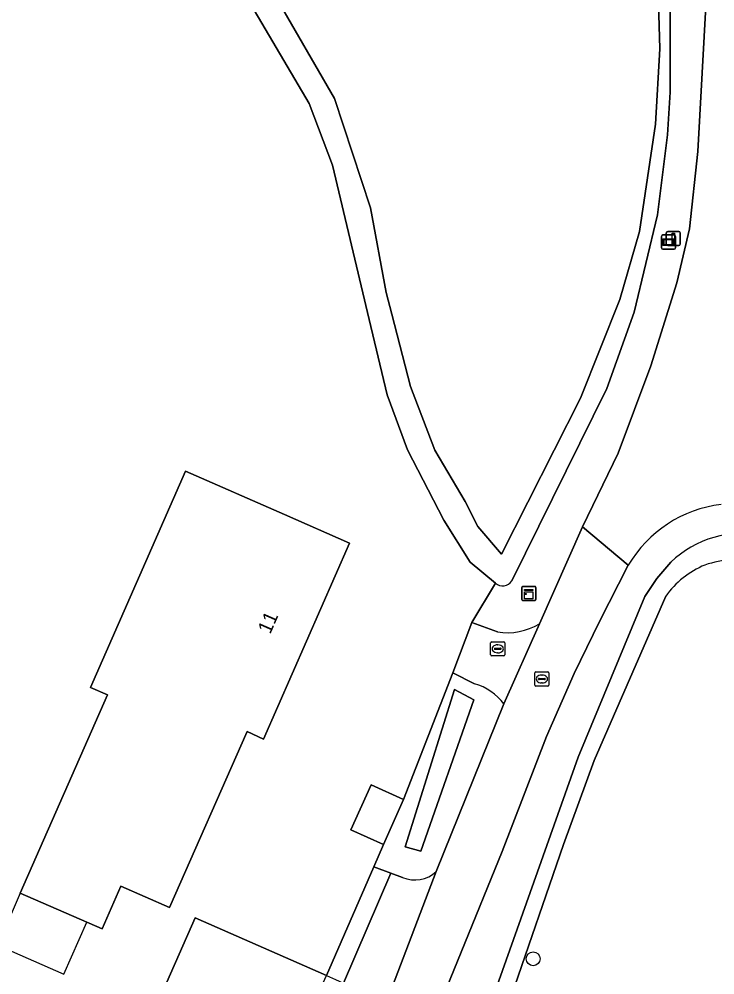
# Model space of a CAD drawing. Extents: x 163859 to 164644, y 379566 to 382155.
# Drawn here: x 164389 to 164438.1, y 381270.8 to 381338.2 of the extents above; entities that cross this region are included whole.
import ezdxf

# ---------------------------------------------------------------- set-up
doc = ezdxf.new("R2010")
doc.units = 0
for name, color, linetype in [('IMGEO_Boom', 7, 'Continuous'), ('IMGEO_Erf', 7, 'Continuous'), ('IMGEO_Groenvoorziening', 7, 'Continuous'), ('IMGEO_Kast', 7, 'Continuous'), ('IMGEO_Pand', 7, 'Continuous'), ('IMGEO_Pand_nummerreeks', 7, 'Continuous'), ('IMGEO_Pand_overbouw', 7, 'Continuous'), ('IMGEO_Rijbaan_lokaal_gesloten', 7, 'Continuous'), ('IMGEO_Rioolput', 7, 'Continuous'), ('IMGEO_Verkeersbordpaal', 7, 'Continuous'), ('IMGEO_Verklikker', 7, 'Continuous'), ('IMGEO_Voetpad_open', 7, 'Continuous'), ('IMGEO_Waterloop', 7, 'Continuous')]:
    doc.layers.add(name, color=color, linetype=linetype)

msp = doc.modelspace()

# ---------------------------------------------------------------- linework, layer by layer
at = {"layer": 'IMGEO_Boom'}
msp.add_circle((164425.258, 381271.924), 0.489, dxfattribs=at)
at = {"layer": 'IMGEO_Erf'}
for points in [[(164388.451, 381245.029), (164391.212, 381242.439), (164394.859, 381239.019), (164397.405, 381243.031), (164407.776, 381264.263), (164398.58, 381268.308), (164401.439, 381274.806), (164410.692, 381270.735), (164414.032, 381278.407), (164414.712, 381279.968), (164412.407, 381281.003), (164413.837, 381284.186), (164416.124, 381283.158), (164419.601, 381292.089), (164420.949, 381295.633), (164422.604, 381298.393), (164420.828, 381299.875), (164418.968, 381302.834), (164416.411, 381307.805), (164414.964, 381311.676), (164413.703, 381316.994), (164411.116, 381327.859), (164409.49, 381332.219), (164399.948, 381348.42)], [(164434.594, 381297.476), (164429.564, 381285.908), (164427.387, 381279.981), (164420.028, 381258.538), (164419.12, 381256.54), (164417.976, 381253.924), (164415.715, 381250), (164411.163, 381242.333), (164409.255, 381239.259), (164409.325, 381239.203), (164403.371, 381230.525), (164405.786, 381228.467), (164414.919, 381240.799), (164435.906, 381232.225), (164447.638, 381227.222), (164449.218, 381234.746), (164455.37, 381233.49), (164476.569, 381225.79), (164468.666, 381207.689), (164466.171, 381201.68), (164476.779, 381197.2)]]:
    msp.add_lwpolyline(points, dxfattribs=at)
msp.add_lwpolyline([(164395.266, 381290.525), (164394.084, 381291.043), (164400.778, 381306.287), (164407.741, 381303.229), (164412.318, 381301.219), (164406.259, 381287.405), (164405.108, 381287.946), (164399.642, 381275.541), (164396.214, 381277.046), (164394.89, 381274.028), (164389.132, 381276.554)], close=True, dxfattribs=at)
for centre, radius, start, end in [((164439.999, 381291.545), 8.555, 81.86677, 108.05094), ((164439.857, 381293.72), 6.465, 112.82995, 144.4846)]:
    msp.add_arc(centre, radius, start, end, dxfattribs=at)
at = {"layer": 'IMGEO_Groenvoorziening'}
for points in [[(164401.574, 381349.362), (164411.254, 381332.57), (164413.803, 381324.847), (164414.912, 381318.899), (164415.306, 381317.364), (164416.618, 381312.275), (164418.341, 381307.767), (164420.475, 381304.145), (164421.353, 381302.387), (164423.018, 381300.443), (164428.593, 381311.446), (164431.363, 381318.402), (164432.75, 381323.18), (164433.882, 381330.758), (164434.191, 381336.078), (164433.566, 381357.04)], [(164425.699, 381295.539), (164428.738, 381302.368), (164431.245, 381307.561), (164433.555, 381313.718), (164435.383, 381319.575), (164436.269, 381323.374), (164436.858, 381328.833), (164437.62, 381342.513)], [(164434.917, 381340.077), (164434.906, 381333.017), (164434.72, 381329.997), (164434.012, 381324.358), (164432.381, 381317.5), (164430.454, 381312.123), (164423.745, 381298.566)], [(164408.093, 381239.754), (164412.866, 381247.752), (164414.21, 381250.168), (164415.85, 381252.761), (164418.248, 381258.03), (164419.865, 381262.136), (164421.914, 381267.784), (164428.425, 381286.135), (164433.135, 381297.466), (164433.959, 381298.733), (164434.95, 381299.874)], [(164431.962, 381299.663), (164429.936, 381295.691), (164428.149, 381292.036), (164426.203, 381287.587), (164423.084, 381279.484), (164417.299, 381265.288), (164413.629, 381256.967), (164407.489, 381245.086), (164401.602, 381236.075), (164380.374, 381209.133), (164373.243, 381200.612), (164368.284, 381194.508), (164366.176, 381192.146), (164356.261, 381180.831), (164355.421, 381179.801), (164327.62, 381145.683), (164299.264, 381110.372), (164285.343, 381092.567), (164271.164, 381074.137), (164257.143, 381055.392), (164248.194, 381042.644), (164246.028, 381039.892)], [(164422.604, 381298.393), (164420.949, 381295.633), (164422.744, 381294.97)], [(164421.124, 381291.309), (164419.601, 381292.089), (164416.124, 381283.158), (164414.712, 381279.968), (164414.032, 381278.407), (164415.235, 381277.962), (164416.06, 381277.657)], [(164418.426, 381278.072), (164423.197, 381289.883)]]:
    msp.add_lwpolyline(points, dxfattribs=at)
msp.add_lwpolyline([(164417.335, 381279.508), (164416.246, 381279.823), (164419.715, 381290.907), (164421.076, 381290.167)], close=True, dxfattribs=at)
for centre, radius, start, end in [((164439.55, 381295.205), 8.801, 96.87712, 149.56303), ((164440.073, 381294.503), 7.422, 78.955, 133.64674), ((164423.103, 381298.949), 0.747, 228.05898, 329.18421), ((164423.459, 381299.216), 4.306, 260.44736, 301.35102), ((164420.058, 381287.539), 3.918, 36.74639, 74.20607), ((164416.931, 381279.643), 2.168, 246.31472, 313.58241)]:
    msp.add_arc(centre, radius, start, end, dxfattribs=at)
at = {"layer": 'IMGEO_Kast'}
for p, q in [((164424.452, 381297.248), (164424.452, 381298.089)), ((164424.452, 381298.089), (164424.452, 381297.248)), ((164424.527, 381298.173), (164425.368, 381298.173)), ((164425.368, 381298.173), (164424.527, 381298.173)), ((164425.452, 381298.098), (164425.452, 381297.257)), ((164425.452, 381297.257), (164425.452, 381298.098)), ((164425.377, 381297.173), (164424.536, 381297.173)), ((164424.536, 381297.173), (164425.377, 381297.173))]:
    msp.add_line(p, q, dxfattribs=at)
for points in [[(164424.647, 381297.963), (164425.247, 381297.963), (164425.247, 381297.878), (164424.647, 381297.878), (164424.647, 381297.963)], [(164424.647, 381297.788), (164425.247, 381297.788), (164425.247, 381297.299), (164424.647, 381297.299), (164424.647, 381297.788)]]:
    msp.add_lwpolyline(points, dxfattribs=at)
msp.add_circle((164424.731, 381297.637), 0.0377, dxfattribs=at)
for centre, start, end in [((164424.53, 381298.095), 92.4484, 184.28452), ((164424.53, 381298.095), 92.4484, 184.28452), ((164425.374, 381298.095), 2.4484, 94.28452), ((164425.374, 381298.095), 2.4484, 94.28452), ((164424.53, 381297.251), 182.4484, 274.28452), ((164424.53, 381297.251), 182.4484, 274.28452), ((164425.374, 381297.251), 272.4484, 4.28452), ((164425.374, 381297.251), 272.4484, 4.28452)]:
    msp.add_arc(centre, 0.0779, start, end, dxfattribs=at)
at = {"layer": 'IMGEO_Pand'}
for points in [[(164412.318, 381301.219), (164407.741, 381303.229), (164400.778, 381306.287), (164394.084, 381291.043), (164395.266, 381290.525), (164389.132, 381276.554), (164394.89, 381274.028), (164396.214, 381277.046), (164399.642, 381275.541), (164405.108, 381287.946), (164406.259, 381287.405)], [(164414.712, 381279.968), (164416.124, 381283.158), (164413.837, 381284.186), (164412.407, 381281.003)], [(164407.776, 381264.263), (164410.692, 381270.735), (164401.439, 381274.806), (164398.58, 381268.308)]]:
    msp.add_lwpolyline(points, close=True, dxfattribs=at)
at = {"layer": 'IMGEO_Pand_overbouw'}
msp.add_lwpolyline([(164393.811, 381274.501), (164389.132, 381276.554), (164387.525, 381272.89), (164392.204, 381270.838)], close=True, dxfattribs=at)
at = {"layer": 'IMGEO_Rijbaan_lokaal_gesloten'}
for points in [[(164445.135, 381404.285), (164445.615, 381444.498), (164445.751, 381455.895), (164445.787, 381457.704), (164442.222, 381457.681), (164442.243, 381448.348), (164442.258, 381444.544), (164442.306, 381432.689), (164442.03, 381410.668), (164440.934, 381376.029), (164437.62, 381342.513), (164436.858, 381328.833), (164436.269, 381323.374), (164435.383, 381319.575), (164433.555, 381313.718), (164431.245, 381307.561), (164428.738, 381302.368), (164431.962, 381299.663)], [(164431.962, 381299.663), (164428.738, 381302.368), (164425.699, 381295.539), (164423.197, 381289.883), (164418.426, 381278.072), (164415.163, 381269.499), (164412.983, 381264.094), (164411.143, 381259.383)], [(164380.374, 381209.133), (164401.602, 381236.075), (164407.489, 381245.086), (164413.629, 381256.967), (164417.299, 381265.288), (164423.084, 381279.484), (164426.203, 381287.587), (164428.149, 381292.036), (164429.936, 381295.691), (164431.962, 381299.663)]]:
    msp.add_lwpolyline(points, dxfattribs=at)
msp.add_arc((164439.55, 381295.205), 8.801, 96.87712, 149.56303, dxfattribs=at)
at = {"layer": 'IMGEO_Rioolput'}
for p, q in [((164422.265, 381293.345), (164422.265, 381294.197)), ((164422.34, 381294.271), (164423.192, 381294.271)), ((164422.524, 381293.765), (164422.524, 381293.777)), ((164422.962, 381293.728), (164422.564, 381293.728)), ((164422.567, 381293.814), (164422.965, 381293.814)), ((164422.753, 381294.051), (164422.778, 381294.051)), ((164423.008, 381293.777), (164423.008, 381293.765)), ((164423.266, 381294.197), (164423.266, 381293.345)), ((164423.192, 381293.271), (164422.34, 381293.271)), ((164422.776, 381293.491), (164422.751, 381293.491)), ((164425.371, 381291.219), (164425.371, 381292.071)), ((164425.446, 381292.145), (164426.298, 381292.145)), ((164425.859, 381291.925), (164425.884, 381291.925)), ((164426.372, 381292.071), (164426.372, 381291.219)), ((164426.298, 381291.145), (164425.446, 381291.145)), ((164425.63, 381291.639), (164425.63, 381291.651)), ((164426.068, 381291.602), (164425.67, 381291.602)), ((164425.673, 381291.688), (164426.071, 381291.688)), ((164425.882, 381291.365), (164425.857, 381291.365)), ((164426.114, 381291.651), (164426.114, 381291.639))]:
    msp.add_line(p, q, dxfattribs=at)
for points in [[(164422.265, 381293.345), (164422.265, 381294.197)], [(164422.34, 381294.271), (164423.192, 381294.271)], [(164423.266, 381294.197), (164423.266, 381293.345)], [(164423.192, 381293.271), (164422.34, 381293.271)], [(164425.371, 381291.219), (164425.371, 381292.071)], [(164425.446, 381292.145), (164426.298, 381292.145)], [(164426.372, 381292.071), (164426.372, 381291.219)], [(164426.298, 381291.145), (164425.446, 381291.145)]]:
    msp.add_lwpolyline(points, dxfattribs=at)
for centre, radius, start, end in [((164422.342, 381294.195), 0.0765, 91.55205, 178.44795), ((164422.342, 381294.195), 0.0765, 91.55205, 178.44795), ((164422.564, 381293.774), 0.0403, 85.87752, 175.75265), ((164422.561, 381293.764), 0.0366, 178.93798, 274.71019), ((164422.965, 381293.771), 0.043, 264.86636, 352.45326), ((164422.969, 381293.776), 0.0386, 1.73085, 96.63898), ((164423.19, 381294.195), 0.0765, 1.55205, 88.44795), ((164423.19, 381294.195), 0.0765, 1.55205, 88.44795), ((164422.342, 381293.347), 0.0765, 181.55205, 268.44795), ((164422.342, 381293.347), 0.0765, 181.55205, 268.44795), ((164423.19, 381293.347), 0.0765, 271.55205, 358.44795), ((164423.19, 381293.347), 0.0765, 271.55205, 358.44795), ((164425.448, 381292.069), 0.0765, 91.55205, 178.44795), ((164425.448, 381292.069), 0.0765, 91.55205, 178.44795), ((164426.296, 381292.069), 0.0765, 1.55205, 88.44795), ((164426.296, 381292.069), 0.0765, 1.55205, 88.44795), ((164425.448, 381291.221), 0.0765, 181.55205, 268.44795), ((164425.448, 381291.221), 0.0765, 181.55205, 268.44795), ((164425.67, 381291.648), 0.0403, 85.87752, 175.75265), ((164425.667, 381291.638), 0.0366, 178.93798, 274.71019), ((164426.071, 381291.645), 0.043, 264.86636, 352.45326), ((164426.075, 381291.65), 0.0386, 1.73085, 96.63898), ((164426.296, 381291.221), 0.0765, 271.55205, 358.44795), ((164426.296, 381291.221), 0.0765, 271.55205, 358.44795)]:
    msp.add_arc(centre, radius, start, end, dxfattribs=at)
for centre, major_axis, ratio, start_param, end_param in [((164422.752, 381293.771), (-0.387, 0.002), 0.722429, 4.712389, 7.853982), ((164422.777, 381293.771), (-0.39, 0.002), 0.717154, 1.570796, 4.712389), ((164425.858, 381291.645), (-0.387, 0.002), 0.722429, 4.712389, 7.853982), ((164425.883, 381291.645), (-0.39, 0.002), 0.717154, 1.570796, 4.712389)]:
    msp.add_ellipse(centre, major_axis=major_axis, ratio=ratio, start_param=start_param, end_param=end_param, dxfattribs=at)
at = {"layer": 'IMGEO_Verkeersbordpaal'}
for p, q in [((164434.634, 381322.299), (164434.634, 381323.099)), ((164434.634, 381323.099), (164434.634, 381322.299)), ((164434.734, 381323.199), (164435.524, 381323.199)), ((164435.524, 381323.199), (164434.734, 381323.199)), ((164435.624, 381323.099), (164435.624, 381322.299)), ((164435.624, 381322.299), (164435.624, 381323.099)), ((164435.524, 381322.199), (164434.734, 381322.199)), ((164434.734, 381322.199), (164435.524, 381322.199))]:
    msp.add_line(p, q, dxfattribs=at)
msp.add_lwpolyline([(164435.054, 381323.074), (164435.204, 381323.074), (164435.204, 381322.324), (164435.054, 381322.324), (164435.054, 381323.074)], dxfattribs=at)
for centre, start, end in [((164434.734, 381323.099), 90, 180), ((164434.734, 381323.099), 90, 180), ((164435.524, 381323.099), 0, 90), ((164435.524, 381323.099), 360, 90), ((164434.734, 381322.299), 180, 270), ((164434.734, 381322.299), 180, 270), ((164435.524, 381322.299), 270, 0), ((164435.524, 381322.299), 270, 0)]:
    msp.add_arc(centre, 0.1, start, end, dxfattribs=at)
at = {"layer": 'IMGEO_Verklikker'}
for p, q in [((164434.301, 381322.044), (164434.301, 381322.844)), ((164434.301, 381322.844), (164434.301, 381322.044)), ((164434.401, 381322.944), (164435.191, 381322.944)), ((164435.191, 381322.944), (164434.401, 381322.944)), ((164435.291, 381322.844), (164435.291, 381322.044)), ((164435.291, 381322.044), (164435.291, 381322.844)), ((164435.191, 381321.944), (164434.401, 381321.944)), ((164434.401, 381321.944), (164435.191, 381321.944))]:
    msp.add_line(p, q, dxfattribs=at)
for points in [[(164434.402, 381322.676), (164435.19, 381322.676), (164435.19, 381322.212), (164434.402, 381322.212), (164434.402, 381322.676)], [(164434.467, 381322.611), (164434.467, 381322.277), (164435.125, 381322.277), (164435.125, 381322.611), (164434.467, 381322.611)]]:
    msp.add_lwpolyline(points, dxfattribs=at)
for centre, start, end in [((164434.401, 381322.844), 90, 180), ((164434.401, 381322.844), 90, 180), ((164435.191, 381322.844), 0, 90), ((164435.191, 381322.844), 360, 90), ((164434.401, 381322.044), 180, 270), ((164434.401, 381322.044), 180, 270), ((164435.191, 381322.044), 270, 0), ((164435.191, 381322.044), 270, 0)]:
    msp.add_arc(centre, 0.1, start, end, dxfattribs=at)
at = {"layer": 'IMGEO_Voetpad_open'}
for points in [[(164422.744, 381294.97), (164420.949, 381295.633), (164419.601, 381292.089), (164421.124, 381291.309)], [(164423.197, 381289.883), (164425.699, 381295.539)], [(164416.06, 381277.657), (164415.235, 381277.962), (164411.898, 381270.209), (164411.969, 381270.189), (164412.86, 381269.935)], [(164415.163, 381269.499), (164418.426, 381278.072)]]:
    msp.add_lwpolyline(points, dxfattribs=at)
msp.add_lwpolyline([(164415.235, 381277.962), (164414.032, 381278.407), (164410.692, 381270.735), (164411.337, 381270.454), (164411.898, 381270.209)], close=True, dxfattribs=at)
for centre, radius, start, end in [((164423.459, 381299.216), 4.306, 260.44736, 301.35102), ((164420.058, 381287.539), 3.918, 36.74639, 74.20607), ((164416.931, 381279.643), 2.168, 246.31472, 313.58241)]:
    msp.add_arc(centre, radius, start, end, dxfattribs=at)
at = {"layer": 'IMGEO_Waterloop'}
for points in [[(164433.566, 381357.04), (164434.191, 381336.078), (164433.882, 381330.758), (164432.75, 381323.18), (164431.363, 381318.402), (164428.593, 381311.446), (164423.018, 381300.443), (164421.353, 381302.387), (164420.475, 381304.145), (164418.341, 381307.767), (164416.618, 381312.275), (164415.306, 381317.364), (164414.912, 381318.899), (164413.803, 381324.847), (164411.254, 381332.57), (164401.574, 381349.362)], [(164399.948, 381348.42), (164409.49, 381332.219), (164411.116, 381327.859), (164413.703, 381316.994), (164414.964, 381311.676), (164416.411, 381307.805), (164418.968, 381302.834), (164420.828, 381299.875), (164422.604, 381298.393)], [(164423.745, 381298.566), (164430.454, 381312.123), (164432.381, 381317.5), (164434.012, 381324.358), (164434.72, 381329.997), (164434.906, 381333.017), (164434.917, 381340.077)], [(164434.95, 381299.874), (164433.959, 381298.733), (164433.135, 381297.466), (164428.425, 381286.135), (164421.914, 381267.784), (164419.865, 381262.136), (164418.248, 381258.03), (164415.85, 381252.761), (164414.21, 381250.168), (164412.866, 381247.752), (164408.093, 381239.754)], [(164409.255, 381239.259), (164411.163, 381242.333), (164415.715, 381250), (164417.976, 381253.924), (164419.12, 381256.54), (164420.028, 381258.538), (164427.387, 381279.981), (164429.564, 381285.908), (164434.594, 381297.476)]]:
    msp.add_lwpolyline(points, dxfattribs=at)
msp.add_lwpolyline([(164417.335, 381279.508), (164421.076, 381290.167), (164419.715, 381290.907), (164416.246, 381279.823)], close=True, dxfattribs=at)
for centre, radius, start, end in [((164440.073, 381294.503), 7.422, 78.955, 133.64674), ((164439.999, 381291.545), 8.555, 81.86677, 108.05094), ((164439.857, 381293.72), 6.465, 112.82995, 144.4846), ((164423.103, 381298.949), 0.747, 228.05898, 329.18421)]:
    msp.add_arc(centre, radius, start, end, dxfattribs=at)

# ---------------------------------------------------------------- texts
at = {"layer": 'IMGEO_Pand_nummerreeks'}
msp.add_text('11', height=1, rotation=66.31986, dxfattribs=at).set_placement((164406.732, 381294.755))

doc.saveas('drawing.dxf')
